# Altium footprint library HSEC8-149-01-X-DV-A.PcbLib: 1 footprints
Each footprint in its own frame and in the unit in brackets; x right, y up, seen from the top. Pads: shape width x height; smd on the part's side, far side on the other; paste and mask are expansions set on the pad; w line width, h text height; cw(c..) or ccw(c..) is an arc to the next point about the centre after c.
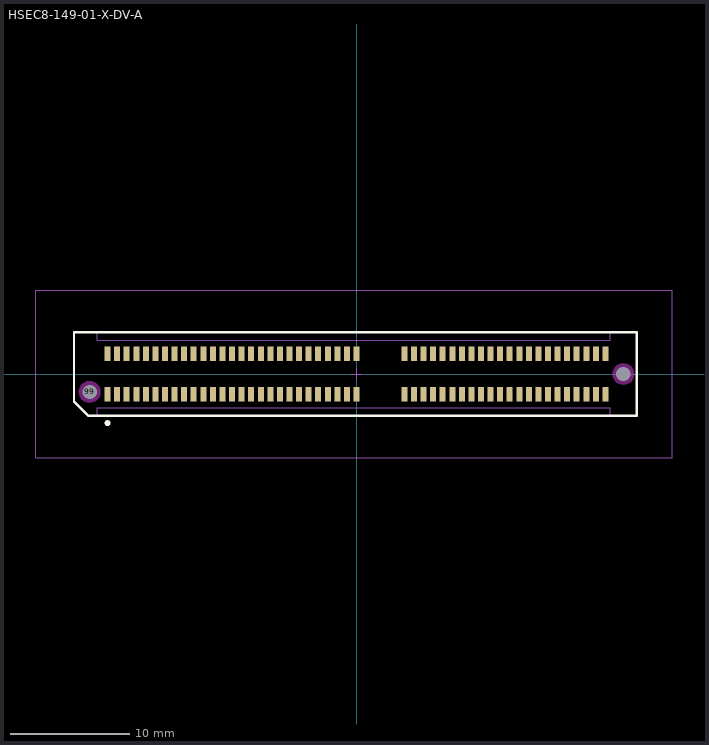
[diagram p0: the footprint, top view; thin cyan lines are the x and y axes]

## HSEC8-149-01-X-DV-A [mm] "0.80mm pitch, 98 pin, hi-speed micro edge card; w/alignment pins"
height 7.98
pads (100):
  rect 0.5x1.2 smd mask+0: 1(-20.8,-1.7) 2(-20.8,1.7) 3(-20,-1.7) 4(-20,1.7) 5(-19.2,-1.7) 6(-19.2,1.7) 7(-18.4,-1.7) 8(-18.4,1.7) 9(-17.6,-1.7) 10(-17.6,1.7) 11(-16.8,-1.7) 12(-16.8,1.7) 13(-16,-1.7) 14(-16,1.7) 15(-15.2,-1.7) 16(-15.2,1.7) 17(-14.4,-1.7) 18(-14.4,1.7) 19(-13.6,-1.7) 20(-13.6,1.7) 21(-12.8,-1.7) 22(-12.8,1.7) 23(-12,-1.7) 24(-12,1.7) 25(-11.2,-1.7) 26(-11.2,1.7) 27(-10.4,-1.7) 28(-10.4,1.7) 29(-9.6,-1.7) 30(-9.6,1.7) 31(-8.8,-1.7) 32(-8.8,1.7) 33(-8,-1.7) 34(-8,1.7) 35(-7.2,-1.7) 36(-7.2,1.7) 37(-6.4,-1.7) 38(-6.4,1.7) 39(-5.6,-1.7) 40(-5.6,1.7) 41(-4.8,-1.7) 42(-4.8,1.7) 43(-4,-1.7) 44(-4,1.7) 45(-3.2,-1.7) 46(-3.2,1.7) 47(-2.4,-1.7) 48(-2.4,1.7) 49(-1.6,-1.7) 50(-1.6,1.7) 51(-0.8,-1.7) 52(-0.8,1.7) 53(0,-1.7) 54(0,1.7) 55(4,-1.7) 56(4,1.7) 57(4.8,-1.7) 58(4.8,1.7) 59(5.6,-1.7) 60(5.6,1.7) 61(6.4,-1.7) 62(6.4,1.7) 63(7.2,-1.7) 64(7.2,1.7) 65(8,-1.7) 66(8,1.7) 67(8.8,-1.7) 68(8.8,1.7) 69(9.6,-1.7) 70(9.6,1.7) 71(10.4,-1.7) 72(10.4,1.7) 73(11.2,-1.7) 74(11.2,1.7) 75(12,-1.7) 76(12,1.7) 77(12.8,-1.7) 78(12.8,1.7) 79(13.6,-1.7) 80(13.6,1.7) 81(14.4,-1.7) 82(14.4,1.7) 83(15.2,-1.7) 84(15.2,1.7) 85(16,-1.7) 86(16,1.7) 87(16.8,-1.7) 88(16.8,1.7) 89(17.6,-1.7) 90(17.6,1.7) 91(18.4,-1.7) 92(18.4,1.7) 93(19.2,-1.7) 94(19.2,1.7) 95(20,-1.7) 96(20,1.7) 97(20.8,-1.7) 98(20.8,1.7)
  round 1 hole 1.2 unplated mask+0: 99(-22.3,-1.5) 100(22.3,0)
Top Overlay:
  circle w0.25: c-20.8,-4.1 r0.125
  lines w0.2: -23.6,-2.3 -23.6,3.5 23.4,3.5 23.4,-3.5 -22.4,-3.5 -23.6,-2.3
Keep-Out Layer:
  pour cut-out: 23.208,0 23.177,0.235 23.086,0.454 22.942,0.642 22.754,0.786 22.535,0.877 22.3,0.908 22.065,0.877 21.846,0.786 21.658,0.642 21.514,0.454 21.423,0.235 21.392,0 21.423,-0.235 21.514,-0.454 21.658,-0.642 21.846,-0.786 22.065,-0.877 22.3,-0.908 22.535,-0.877 22.754,-0.786 22.942,-0.642 23.086,-0.454 23.177,-0.235
  pour cut-out: -21.392,-1.5 -21.423,-1.265 -21.514,-1.046 -21.658,-0.858 -21.846,-0.714 -22.065,-0.623 -22.3,-0.592 -22.535,-0.623 -22.754,-0.714 -22.942,-0.858 -23.086,-1.046 -23.177,-1.265 -23.208,-1.5 -23.177,-1.735 -23.086,-1.954 -22.942,-2.142 -22.754,-2.286 -22.535,-2.377 -22.3,-2.408 -22.065,-2.377 -21.846,-2.286 -21.658,-2.142 -21.514,-1.954 -21.423,-1.735
Mechanical 12:
  lines w0.001: -23.6,-2.3 -23.6,3.5 23.4,3.5 23.4,-3.5 -22.4,-3.5 -23.6,-2.3
Mechanical 13:
  lines w0.1: -23.6,-2.3 -23.6,3.5 -21.65,3.505 -21.65,2.8 21.2,2.8 21.2,3.5 23.4,3.5 23.4,-3.5 21.2,-3.5 21.2,-2.8 -21.65,-2.8 -21.65,-3.5 -22.4,-3.5 -23.6,-2.3
  text ".Designator" at 0.254,0.254 h1.52
Mechanical 15:
  lines w0.05: -0.5,0 0.5,0 ; 0,-0.5 0,0.5 ; -26.794,-7 -26.794,7 26.375,7 26.375,-7 -26.794,-7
